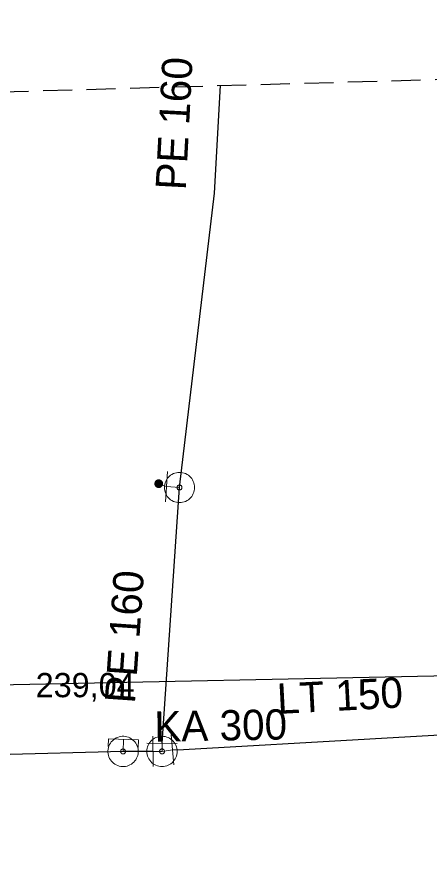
# Model space of a CAD drawing. Extents: x -777996 to -777727, y -976581 to -976199.
# Drawn here: x -777934.38 to -777920.74, y -976227.07 to -976198.85 of the extents above; entities that cross this region are included whole.
import ezdxf

# ---------------------------------------------------------------- set-up
doc = ezdxf.new("R2010")
doc.units = 0
doc.header["$LTSCALE"] = 0.32
doc.linetypes.add('MEDIUM_DASHED', pattern=[4.5, 3, -1.5])
for name, color, linetype, lineweight in [('1', 7, 'MEDIUM_DASHED', 25), ('14', 7, 'Continuous', 25), ('17', 7, 'Continuous', 25), ('34', 7, 'Continuous', 13), ('47', 7, 'Continuous', 13), ('9', 7, 'Continuous', 13)]:
    doc.layers.add(name, color=color, linetype=linetype, lineweight=lineweight)

msp = doc.modelspace()

# ---------------------------------------------------------------- linework, layer by layer
at = {"layer": '1'}
msp.add_lwpolyline([(-777995.417, -976203.033), (-777848.18, -976198.846), (-777864.927, -976230.247), (-777726.762, -976491.225), (-777789.565, -976581.242), (-777941.686, -976558.215), (-777989.136, -976405.396)], close=True, dxfattribs=at)
at = {"layer": '14', "lineweight": 13}
for p, q in [((-777929.438, -976214.347), (-777929.699, -976214.25)), ((-777929.438, -976214.347), (-777929.013, -976214.376)), ((-777930.877, -976223.09), (-777930.861, -976222.69)), ((-777929.59, -976222.82), (-777929.59, -976223.088)), ((-777929.59, -976223.088), (-777929.89, -976223.087)), ((-777929.59, -976223.088), (-777929.246, -976223.038))]:
    msp.add_line(p, q, dxfattribs=at)
at = {"layer": '14'}
msp.add_line((-777935.509, -976220.899), (-777918.245, -976220.55), dxfattribs=at)
at = {"layer": '17'}
for p, q in [((-777929.59, -976222.82), (-777929.013, -976214.376)), ((-777930.877, -976223.09), (-777935.637, -976223.213)), ((-777929.89, -976223.087), (-777930.877, -976223.09))]:
    msp.add_line(p, q, dxfattribs=at)
for points in [[(-777929.013, -976214.376), (-777927.859, -976204.66), (-777927.663, -976201.106)], [(-777929.246, -976223.038), (-777928.877, -976223.029), (-777916.57, -976222.32), (-777916.18, -976222.3)]]:
    msp.add_lwpolyline(points, dxfattribs=at)
at = {"layer": '34'}
for p, q in [((-777929.404, -976213.848), (-777929.472, -976214.845)), ((-777929.205, -976223.536), (-777929.285, -976222.539)), ((-777930.089, -976222.818), (-777929.09, -976222.822)), ((-777929.888, -976223.586), (-777929.89, -976222.587))]:
    msp.add_line(p, q, dxfattribs=at)
at = {"layer": '47'}
for points in [[(-777928.513, -976214.376), (-777928.516, -976214.324), (-777928.524, -976214.272), (-777928.538, -976214.222), (-777928.556, -976214.173), (-777928.58, -976214.126), (-777928.609, -976214.082), (-777928.642, -976214.042), (-777928.679, -976214.005), (-777928.719, -976213.972), (-777928.763, -976213.943), (-777928.81, -976213.919), (-777928.859, -976213.901), (-777928.909, -976213.887), (-777928.961, -976213.879), (-777929.013, -976213.876), (-777929.065, -976213.879), (-777929.117, -976213.887), (-777929.168, -976213.901), (-777929.216, -976213.919), (-777929.263, -976213.943), (-777929.307, -976213.972), (-777929.348, -976214.005), (-777929.385, -976214.042), (-777929.418, -976214.082), (-777929.446, -976214.126), (-777929.47, -976214.173), (-777929.489, -976214.222), (-777929.502, -976214.272), (-777929.51, -976214.324), (-777929.513, -976214.376), (-777929.51, -976214.428), (-777929.502, -976214.48), (-777929.489, -976214.531), (-777929.47, -976214.579), (-777929.446, -976214.626), (-777929.418, -976214.67), (-777929.385, -976214.711), (-777929.348, -976214.748), (-777929.307, -976214.781), (-777929.263, -976214.809), (-777929.216, -976214.833), (-777929.168, -976214.852), (-777929.117, -976214.865), (-777929.065, -976214.873), (-777929.013, -976214.876), (-777928.961, -976214.873), (-777928.909, -976214.865), (-777928.859, -976214.852), (-777928.81, -976214.833), (-777928.763, -976214.809), (-777928.719, -976214.781), (-777928.679, -976214.748), (-777928.642, -976214.711), (-777928.609, -976214.67), (-777928.58, -976214.626), (-777928.556, -976214.579), (-777928.538, -976214.531), (-777928.524, -976214.48), (-777928.516, -976214.428)], [(-777928.931, -976214.376), (-777928.931, -976214.367), (-777928.933, -976214.359), (-777928.935, -976214.351), (-777928.938, -976214.343), (-777928.942, -976214.335), (-777928.947, -976214.328), (-777928.952, -976214.321), (-777928.958, -976214.315), (-777928.965, -976214.31), (-777928.972, -976214.305), (-777928.98, -976214.301), (-777928.988, -976214.298), (-777928.996, -976214.296), (-777929.004, -976214.294), (-777929.013, -976214.294), (-777929.022, -976214.294), (-777929.03, -976214.296), (-777929.038, -976214.298), (-777929.046, -976214.301), (-777929.054, -976214.305), (-777929.061, -976214.31), (-777929.068, -976214.315), (-777929.074, -976214.321), (-777929.08, -976214.328), (-777929.084, -976214.335), (-777929.088, -976214.343), (-777929.091, -976214.351), (-777929.093, -976214.359), (-777929.095, -976214.367), (-777929.095, -976214.376), (-777929.095, -976214.385), (-777929.093, -976214.393), (-777929.091, -976214.401), (-777929.088, -976214.409), (-777929.084, -976214.417), (-777929.08, -976214.424), (-777929.074, -976214.431), (-777929.068, -976214.437), (-777929.061, -976214.443), (-777929.054, -976214.447), (-777929.046, -976214.451), (-777929.038, -976214.454), (-777929.03, -976214.456), (-777929.022, -976214.458), (-777929.013, -976214.458), (-777929.004, -976214.458), (-777928.996, -976214.456), (-777928.988, -976214.454), (-777928.98, -976214.451), (-777928.972, -976214.447), (-777928.965, -976214.443), (-777928.958, -976214.437), (-777928.952, -976214.431), (-777928.947, -976214.424), (-777928.942, -976214.417), (-777928.938, -976214.409), (-777928.935, -976214.401), (-777928.933, -976214.393), (-777928.931, -976214.385)], [(-777930.377, -976223.063), (-777930.383, -976223.011), (-777930.394, -976222.959), (-777930.41, -976222.91), (-777930.431, -976222.862), (-777930.458, -976222.817), (-777930.489, -976222.774), (-777930.524, -976222.736), (-777930.563, -976222.701), (-777930.605, -976222.67), (-777930.65, -976222.644), (-777930.698, -976222.622), (-777930.748, -976222.607), (-777930.799, -976222.596), (-777930.851, -976222.59), (-777930.903, -976222.59), (-777930.955, -976222.596), (-777931.007, -976222.607), (-777931.057, -976222.624), (-777931.104, -976222.644), (-777931.149, -976222.671), (-777931.192, -976222.702), (-777931.231, -976222.737), (-777931.266, -976222.776), (-777931.297, -976222.818), (-777931.322, -976222.863), (-777931.344, -976222.911), (-777931.36, -976222.961), (-777931.37, -976223.012), (-777931.376, -976223.064), (-777931.376, -976223.116), (-777931.37, -976223.168), (-777931.359, -976223.22), (-777931.343, -976223.27), (-777931.322, -976223.317), (-777931.295, -976223.362), (-777931.265, -976223.405), (-777931.23, -976223.444), (-777931.191, -976223.479), (-777931.148, -976223.51), (-777931.103, -976223.535), (-777931.055, -976223.557), (-777931.006, -976223.573), (-777930.954, -976223.583), (-777930.902, -976223.589), (-777930.85, -976223.589), (-777930.798, -976223.583), (-777930.746, -976223.572), (-777930.697, -976223.557), (-777930.649, -976223.535), (-777930.604, -976223.508), (-777930.561, -976223.478), (-777930.523, -976223.443), (-777930.488, -976223.404), (-777930.457, -976223.361), (-777930.431, -976223.316), (-777930.409, -976223.268), (-777930.394, -976223.219), (-777930.383, -976223.167), (-777930.377, -976223.115)], [(-777929.09, -976223.088), (-777929.093, -976223.036), (-777929.101, -976222.983), (-777929.115, -976222.934), (-777929.132, -976222.885), (-777929.157, -976222.838), (-777929.186, -976222.794), (-777929.218, -976222.754), (-777929.255, -976222.717), (-777929.296, -976222.684), (-777929.34, -976222.655), (-777929.387, -976222.63), (-777929.436, -976222.613), (-777929.485, -976222.599), (-777929.538, -976222.591), (-777929.59, -976222.588), (-777929.642, -976222.591), (-777929.694, -976222.599), (-777929.745, -976222.613), (-777929.793, -976222.63), (-777929.84, -976222.655), (-777929.884, -976222.684), (-777929.924, -976222.717), (-777929.962, -976222.754), (-777929.995, -976222.794), (-777930.022, -976222.838), (-777930.047, -976222.885), (-777930.066, -976222.934), (-777930.078, -976222.983), (-777930.087, -976223.036), (-777930.09, -976223.088), (-777930.087, -976223.14), (-777930.078, -976223.192), (-777930.066, -976223.243), (-777930.047, -976223.291), (-777930.022, -976223.338), (-777929.995, -976223.382), (-777929.962, -976223.423), (-777929.924, -976223.46), (-777929.884, -976223.493), (-777929.84, -976223.521), (-777929.793, -976223.545), (-777929.745, -976223.564), (-777929.694, -976223.576), (-777929.642, -976223.585), (-777929.59, -976223.588), (-777929.538, -976223.585), (-777929.485, -976223.576), (-777929.436, -976223.564), (-777929.387, -976223.545), (-777929.34, -976223.521), (-777929.296, -976223.493), (-777929.255, -976223.46), (-777929.218, -976223.423), (-777929.186, -976223.382), (-777929.157, -976223.338), (-777929.132, -976223.291), (-777929.115, -976223.243), (-777929.101, -976223.192), (-777929.093, -976223.14)], [(-777930.795, -976223.085), (-777930.795, -976223.076), (-777930.798, -976223.068), (-777930.8, -976223.06), (-777930.803, -976223.053), (-777930.808, -976223.045), (-777930.813, -976223.038), (-777930.819, -976223.031), (-777930.825, -976223.026), (-777930.832, -976223.021), (-777930.839, -976223.016), (-777930.848, -976223.013), (-777930.856, -976223.01), (-777930.864, -976223.009), (-777930.872, -976223.007), (-777930.881, -976223.008), (-777930.89, -976223.008), (-777930.898, -976223.011), (-777930.906, -976223.013), (-777930.913, -976223.016), (-777930.921, -976223.021), (-777930.928, -976223.026), (-777930.935, -976223.032), (-777930.94, -976223.038), (-777930.946, -976223.045), (-777930.95, -976223.052), (-777930.953, -976223.061), (-777930.956, -976223.069), (-777930.957, -976223.077), (-777930.959, -976223.085), (-777930.958, -976223.094), (-777930.958, -976223.103), (-777930.955, -976223.111), (-777930.953, -976223.119), (-777930.95, -976223.126), (-777930.945, -976223.134), (-777930.941, -976223.141), (-777930.934, -976223.148), (-777930.928, -976223.153), (-777930.921, -976223.159), (-777930.914, -976223.163), (-777930.905, -976223.166), (-777930.897, -976223.169), (-777930.889, -976223.17), (-777930.881, -976223.172), (-777930.872, -976223.171), (-777930.863, -976223.171), (-777930.855, -976223.168), (-777930.847, -976223.166), (-777930.84, -976223.163), (-777930.832, -976223.158), (-777930.825, -976223.154), (-777930.818, -976223.147), (-777930.813, -976223.141), (-777930.808, -976223.134), (-777930.803, -976223.127), (-777930.8, -976223.118), (-777930.797, -976223.11), (-777930.796, -976223.102), (-777930.794, -976223.094)], [(-777929.507, -976223.088), (-777929.507, -976223.079), (-777929.51, -976223.071), (-777929.512, -976223.063), (-777929.515, -976223.054), (-777929.519, -976223.047), (-777929.524, -976223.04), (-777929.529, -976223.032), (-777929.534, -976223.027), (-777929.542, -976223.022), (-777929.549, -976223.017), (-777929.556, -976223.013), (-777929.565, -976223.01), (-777929.573, -976223.008), (-777929.581, -976223.005), (-777929.59, -976223.005), (-777929.598, -976223.005), (-777929.607, -976223.008), (-777929.615, -976223.01), (-777929.623, -976223.013), (-777929.63, -976223.017), (-777929.637, -976223.022), (-777929.645, -976223.027), (-777929.651, -976223.032), (-777929.657, -976223.04), (-777929.661, -976223.047), (-777929.664, -976223.054), (-777929.668, -976223.063), (-777929.669, -976223.071), (-777929.672, -976223.079), (-777929.672, -976223.088), (-777929.672, -976223.097), (-777929.669, -976223.105), (-777929.668, -976223.113), (-777929.664, -976223.121), (-777929.661, -976223.129), (-777929.657, -976223.136), (-777929.651, -976223.143), (-777929.645, -976223.149), (-777929.637, -976223.155), (-777929.63, -976223.159), (-777929.623, -976223.163), (-777929.615, -976223.166), (-777929.607, -976223.168), (-777929.598, -976223.17), (-777929.59, -976223.17), (-777929.581, -976223.17), (-777929.573, -976223.168), (-777929.565, -976223.166), (-777929.556, -976223.163), (-777929.549, -976223.159), (-777929.542, -976223.155), (-777929.534, -976223.149), (-777929.529, -976223.143), (-777929.524, -976223.136), (-777929.519, -976223.129), (-777929.515, -976223.121), (-777929.512, -976223.113), (-777929.51, -976223.105), (-777929.507, -976223.097)]]:
    msp.add_lwpolyline(points, close=True, dxfattribs=at)
msp.add_lwpolyline([(-777931.366, -976222.922), (-777931.356, -976222.67), (-777930.365, -976222.709), (-777930.375, -976222.96)], dxfattribs=at)
at = {"layer": '9'}
for points in [[(-777929.825, -976214.25), (-777929.825, -976214.263), (-777929.823, -976214.276), (-777929.82, -976214.289), (-777929.815, -976214.301), (-777929.809, -976214.313), (-777929.802, -976214.324), (-777929.794, -976214.334), (-777929.784, -976214.344), (-777929.774, -976214.352), (-777929.763, -976214.359), (-777929.751, -976214.365), (-777929.739, -976214.37), (-777929.726, -976214.373), (-777929.713, -976214.375), (-777929.7, -976214.377), (-777929.687, -976214.376), (-777929.674, -976214.374), (-777929.661, -976214.371), (-777929.649, -976214.366), (-777929.637, -976214.36), (-777929.626, -976214.353), (-777929.616, -976214.345), (-777929.606, -976214.335), (-777929.598, -976214.325), (-777929.591, -976214.314), (-777929.585, -976214.302), (-777929.58, -976214.29), (-777929.577, -976214.277), (-777929.575, -976214.264), (-777929.573, -976214.251), (-777929.574, -976214.238), (-777929.576, -976214.225), (-777929.579, -976214.212), (-777929.584, -976214.2), (-777929.59, -976214.188), (-777929.597, -976214.177), (-777929.605, -976214.167), (-777929.615, -976214.157), (-777929.625, -976214.149), (-777929.636, -976214.142), (-777929.648, -976214.136), (-777929.66, -976214.131), (-777929.673, -976214.128), (-777929.686, -976214.126), (-777929.699, -976214.125), (-777929.712, -976214.125), (-777929.725, -976214.127), (-777929.738, -976214.13), (-777929.75, -976214.135), (-777929.762, -976214.141), (-777929.773, -976214.148), (-777929.783, -976214.156), (-777929.793, -976214.166), (-777929.801, -976214.176), (-777929.808, -976214.187), (-777929.814, -976214.199), (-777929.819, -976214.211), (-777929.822, -976214.224), (-777929.824, -976214.237)], [(-777929.805, -976214.25), (-777929.806, -976214.261), (-777929.804, -976214.272), (-777929.801, -976214.283), (-777929.797, -976214.293), (-777929.792, -976214.303), (-777929.786, -976214.312), (-777929.779, -976214.321), (-777929.771, -976214.329), (-777929.762, -976214.336), (-777929.753, -976214.342), (-777929.743, -976214.347), (-777929.733, -976214.351), (-777929.722, -976214.354), (-777929.711, -976214.357), (-777929.7, -976214.357), (-777929.689, -976214.357), (-777929.678, -976214.355), (-777929.667, -976214.352), (-777929.657, -976214.348), (-777929.647, -976214.343), (-777929.638, -976214.337), (-777929.629, -976214.33), (-777929.621, -976214.322), (-777929.614, -976214.313), (-777929.608, -976214.304), (-777929.603, -976214.294), (-777929.599, -976214.284), (-777929.596, -976214.273), (-777929.594, -976214.262), (-777929.593, -976214.251), (-777929.593, -976214.24), (-777929.595, -976214.229), (-777929.598, -976214.218), (-777929.602, -976214.208), (-777929.607, -976214.198), (-777929.613, -976214.189), (-777929.62, -976214.18), (-777929.628, -976214.172), (-777929.637, -976214.165), (-777929.646, -976214.159), (-777929.656, -976214.154), (-777929.666, -976214.15), (-777929.677, -976214.147), (-777929.688, -976214.145), (-777929.699, -976214.145), (-777929.71, -976214.144), (-777929.721, -976214.146), (-777929.732, -976214.149), (-777929.742, -976214.153), (-777929.752, -976214.158), (-777929.761, -976214.164), (-777929.77, -976214.171), (-777929.778, -976214.179), (-777929.785, -976214.188), (-777929.791, -976214.197), (-777929.796, -976214.207), (-777929.8, -976214.217), (-777929.803, -976214.228), (-777929.805, -976214.239)], [(-777929.786, -976214.25), (-777929.786, -976214.259), (-777929.785, -976214.268), (-777929.782, -976214.277), (-777929.779, -976214.285), (-777929.775, -976214.293), (-777929.77, -976214.301), (-777929.764, -976214.308), (-777929.758, -976214.314), (-777929.751, -976214.32), (-777929.743, -976214.325), (-777929.735, -976214.329), (-777929.727, -976214.332), (-777929.718, -976214.335), (-777929.709, -976214.336), (-777929.7, -976214.338), (-777929.691, -976214.337), (-777929.682, -976214.336), (-777929.673, -976214.333), (-777929.665, -976214.33), (-777929.657, -976214.326), (-777929.649, -976214.321), (-777929.642, -976214.315), (-777929.636, -976214.309), (-777929.63, -976214.302), (-777929.625, -976214.294), (-777929.621, -976214.286), (-777929.618, -976214.278), (-777929.615, -976214.269), (-777929.614, -976214.26), (-777929.612, -976214.251), (-777929.613, -976214.242), (-777929.614, -976214.233), (-777929.617, -976214.224), (-777929.62, -976214.216), (-777929.624, -976214.208), (-777929.629, -976214.2), (-777929.635, -976214.193), (-777929.641, -976214.187), (-777929.648, -976214.181), (-777929.656, -976214.176), (-777929.664, -976214.172), (-777929.672, -976214.169), (-777929.681, -976214.166), (-777929.69, -976214.165), (-777929.699, -976214.164), (-777929.708, -976214.164), (-777929.717, -976214.165), (-777929.726, -976214.168), (-777929.734, -976214.171), (-777929.742, -976214.175), (-777929.75, -976214.18), (-777929.757, -976214.186), (-777929.763, -976214.192), (-777929.769, -976214.199), (-777929.774, -976214.207), (-777929.778, -976214.215), (-777929.781, -976214.223), (-777929.784, -976214.232), (-777929.785, -976214.241)], [(-777929.766, -976214.25), (-777929.766, -976214.257), (-777929.765, -976214.264), (-777929.764, -976214.271), (-777929.761, -976214.277), (-777929.758, -976214.283), (-777929.754, -976214.289), (-777929.75, -976214.295), (-777929.745, -976214.3), (-777929.739, -976214.304), (-777929.733, -976214.308), (-777929.727, -976214.311), (-777929.721, -976214.314), (-777929.714, -976214.315), (-777929.707, -976214.318), (-777929.7, -976214.318), (-777929.693, -976214.318), (-777929.686, -976214.316), (-777929.679, -976214.315), (-777929.673, -976214.312), (-777929.666, -976214.309), (-777929.661, -976214.305), (-777929.655, -976214.301), (-777929.65, -976214.296), (-777929.646, -976214.29), (-777929.642, -976214.284), (-777929.639, -976214.278), (-777929.636, -976214.272), (-777929.634, -976214.265), (-777929.633, -976214.258), (-777929.632, -976214.251), (-777929.632, -976214.244), (-777929.633, -976214.237), (-777929.635, -976214.23), (-777929.638, -976214.224), (-777929.641, -976214.217), (-777929.645, -976214.212), (-777929.649, -976214.206), (-777929.654, -976214.201), (-777929.66, -976214.197), (-777929.665, -976214.193), (-777929.672, -976214.19), (-777929.678, -976214.187), (-777929.685, -976214.185), (-777929.692, -976214.184), (-777929.699, -976214.184), (-777929.706, -976214.184), (-777929.713, -976214.184), (-777929.72, -976214.186), (-777929.726, -976214.189), (-777929.732, -976214.192), (-777929.738, -976214.196), (-777929.744, -976214.2), (-777929.749, -976214.205), (-777929.753, -976214.211), (-777929.757, -976214.216), (-777929.76, -976214.223), (-777929.763, -976214.229), (-777929.764, -976214.236), (-777929.766, -976214.243)], [(-777929.746, -976214.25), (-777929.746, -976214.255), (-777929.746, -976214.26), (-777929.745, -976214.265), (-777929.743, -976214.269), (-777929.741, -976214.274), (-777929.738, -976214.278), (-777929.735, -976214.281), (-777929.731, -976214.285), (-777929.728, -976214.288), (-777929.724, -976214.291), (-777929.719, -976214.293), (-777929.715, -976214.295), (-777929.71, -976214.296), (-777929.705, -976214.298), (-777929.7, -976214.298), (-777929.695, -976214.298), (-777929.69, -976214.297), (-777929.685, -976214.296), (-777929.681, -976214.294), (-777929.676, -976214.292), (-777929.672, -976214.289), (-777929.668, -976214.286), (-777929.665, -976214.282), (-777929.662, -976214.279), (-777929.659, -976214.275), (-777929.657, -976214.27), (-777929.655, -976214.266), (-777929.654, -976214.261), (-777929.653, -976214.256), (-777929.652, -976214.251), (-777929.652, -976214.246), (-777929.653, -976214.241), (-777929.654, -976214.236), (-777929.656, -976214.232), (-777929.658, -976214.227), (-777929.661, -976214.223), (-777929.664, -976214.219), (-777929.667, -976214.216), (-777929.671, -976214.213), (-777929.675, -976214.21), (-777929.68, -976214.208), (-777929.684, -976214.206), (-777929.689, -976214.205), (-777929.694, -976214.204), (-777929.699, -976214.204), (-777929.704, -976214.204), (-777929.709, -976214.205), (-777929.714, -976214.205), (-777929.718, -976214.207), (-777929.723, -976214.209), (-777929.727, -976214.212), (-777929.73, -976214.215), (-777929.734, -976214.218), (-777929.737, -976214.222), (-777929.74, -976214.226), (-777929.742, -976214.231), (-777929.744, -976214.235), (-777929.745, -976214.24), (-777929.746, -976214.245)], [(-777929.726, -976214.25), (-777929.726, -976214.253), (-777929.727, -976214.256), (-777929.726, -976214.258), (-777929.725, -976214.261), (-777929.724, -976214.264), (-777929.722, -976214.266), (-777929.72, -976214.268), (-777929.718, -976214.27), (-777929.716, -976214.272), (-777929.714, -976214.274), (-777929.711, -976214.276), (-777929.708, -976214.277), (-777929.706, -976214.277), (-777929.703, -976214.278), (-777929.7, -976214.278), (-777929.697, -976214.278), (-777929.694, -976214.278), (-777929.691, -976214.277), (-777929.689, -976214.276), (-777929.686, -976214.275), (-777929.684, -976214.273), (-777929.681, -976214.271), (-777929.679, -976214.269), (-777929.678, -976214.267), (-777929.676, -976214.265), (-777929.675, -976214.262), (-777929.673, -976214.259), (-777929.673, -976214.257), (-777929.672, -976214.254), (-777929.671, -976214.251), (-777929.672, -976214.248), (-777929.672, -976214.245), (-777929.673, -976214.242), (-777929.674, -976214.24), (-777929.675, -976214.237), (-777929.677, -976214.235), (-777929.678, -976214.232), (-777929.68, -976214.23), (-777929.683, -976214.229), (-777929.685, -976214.227), (-777929.688, -976214.226), (-777929.69, -976214.225), (-777929.693, -976214.224), (-777929.696, -976214.224), (-777929.699, -976214.223), (-777929.702, -976214.224), (-777929.705, -976214.223), (-777929.707, -976214.225), (-777929.71, -976214.225), (-777929.713, -976214.226), (-777929.715, -976214.228), (-777929.717, -976214.229), (-777929.719, -976214.231), (-777929.721, -976214.234), (-777929.723, -976214.236), (-777929.724, -976214.239), (-777929.725, -976214.241), (-777929.726, -976214.244), (-777929.726, -976214.247)], [(-777929.707, -976214.25), (-777929.707, -976214.252), (-777929.707, -976214.252), (-777929.706, -976214.252), (-777929.706, -976214.254), (-777929.707, -976214.255), (-777929.705, -976214.255), (-777929.705, -976214.255), (-777929.705, -976214.257), (-777929.705, -976214.257), (-777929.704, -976214.258), (-777929.702, -976214.258), (-777929.702, -976214.258), (-777929.702, -976214.259), (-777929.7, -976214.259), (-777929.7, -976214.259), (-777929.699, -976214.259), (-777929.698, -976214.259), (-777929.698, -976214.258), (-777929.697, -976214.258), (-777929.695, -976214.258), (-777929.695, -976214.257), (-777929.695, -976214.257), (-777929.694, -976214.256), (-777929.694, -976214.256), (-777929.692, -976214.255), (-777929.692, -976214.254), (-777929.691, -976214.253), (-777929.691, -976214.253), (-777929.691, -976214.252), (-777929.691, -976214.251), (-777929.691, -976214.25), (-777929.691, -976214.249), (-777929.691, -976214.249), (-777929.692, -976214.248), (-777929.692, -976214.247), (-777929.693, -976214.246), (-777929.693, -976214.246), (-777929.694, -976214.245), (-777929.694, -976214.245), (-777929.695, -976214.244), (-777929.696, -976214.244), (-777929.697, -976214.243), (-777929.697, -976214.243), (-777929.698, -976214.243), (-777929.699, -976214.243), (-777929.7, -976214.243), (-777929.701, -976214.243), (-777929.701, -976214.243), (-777929.702, -976214.244), (-777929.703, -976214.243), (-777929.704, -976214.245), (-777929.704, -976214.245), (-777929.705, -976214.245), (-777929.705, -976214.245), (-777929.706, -976214.247), (-777929.706, -976214.248), (-777929.706, -976214.249), (-777929.707, -976214.249), (-777929.707, -976214.25)]]:
    msp.add_lwpolyline(points, close=True, dxfattribs=at)

# ---------------------------------------------------------------- texts
at = {"layer": '1'}
for s, rotation, p in [('PE 160', 87, (-777928.807, -976204.573)), ('PE 160', 86, (-777930.488, -976221.524)), ('LT 150', 3, (-777925.764, -976221.852)), ('KA 300', 1, (-777929.836, -976222.769))]:
    msp.add_text(s, height=1, rotation=rotation, dxfattribs=at).set_placement(p)
msp.add_text('239,04', height=0.8, dxfattribs=at).set_placement((-777933.766, -976221.299))

doc.saveas('drawing.dxf')
